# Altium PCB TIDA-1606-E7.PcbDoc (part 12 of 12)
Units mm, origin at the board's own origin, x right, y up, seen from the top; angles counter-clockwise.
Board outline 270 x 345 mm, 4 copper layers (Top Layer, Signal Layer 1, Signal Layer 2, Bottom Layer), stack 2.326 mm thick; 1282 components, 576 nets, 3628 pads, 4132 vias.
Unrouted connection lines stored in the file: 1719.
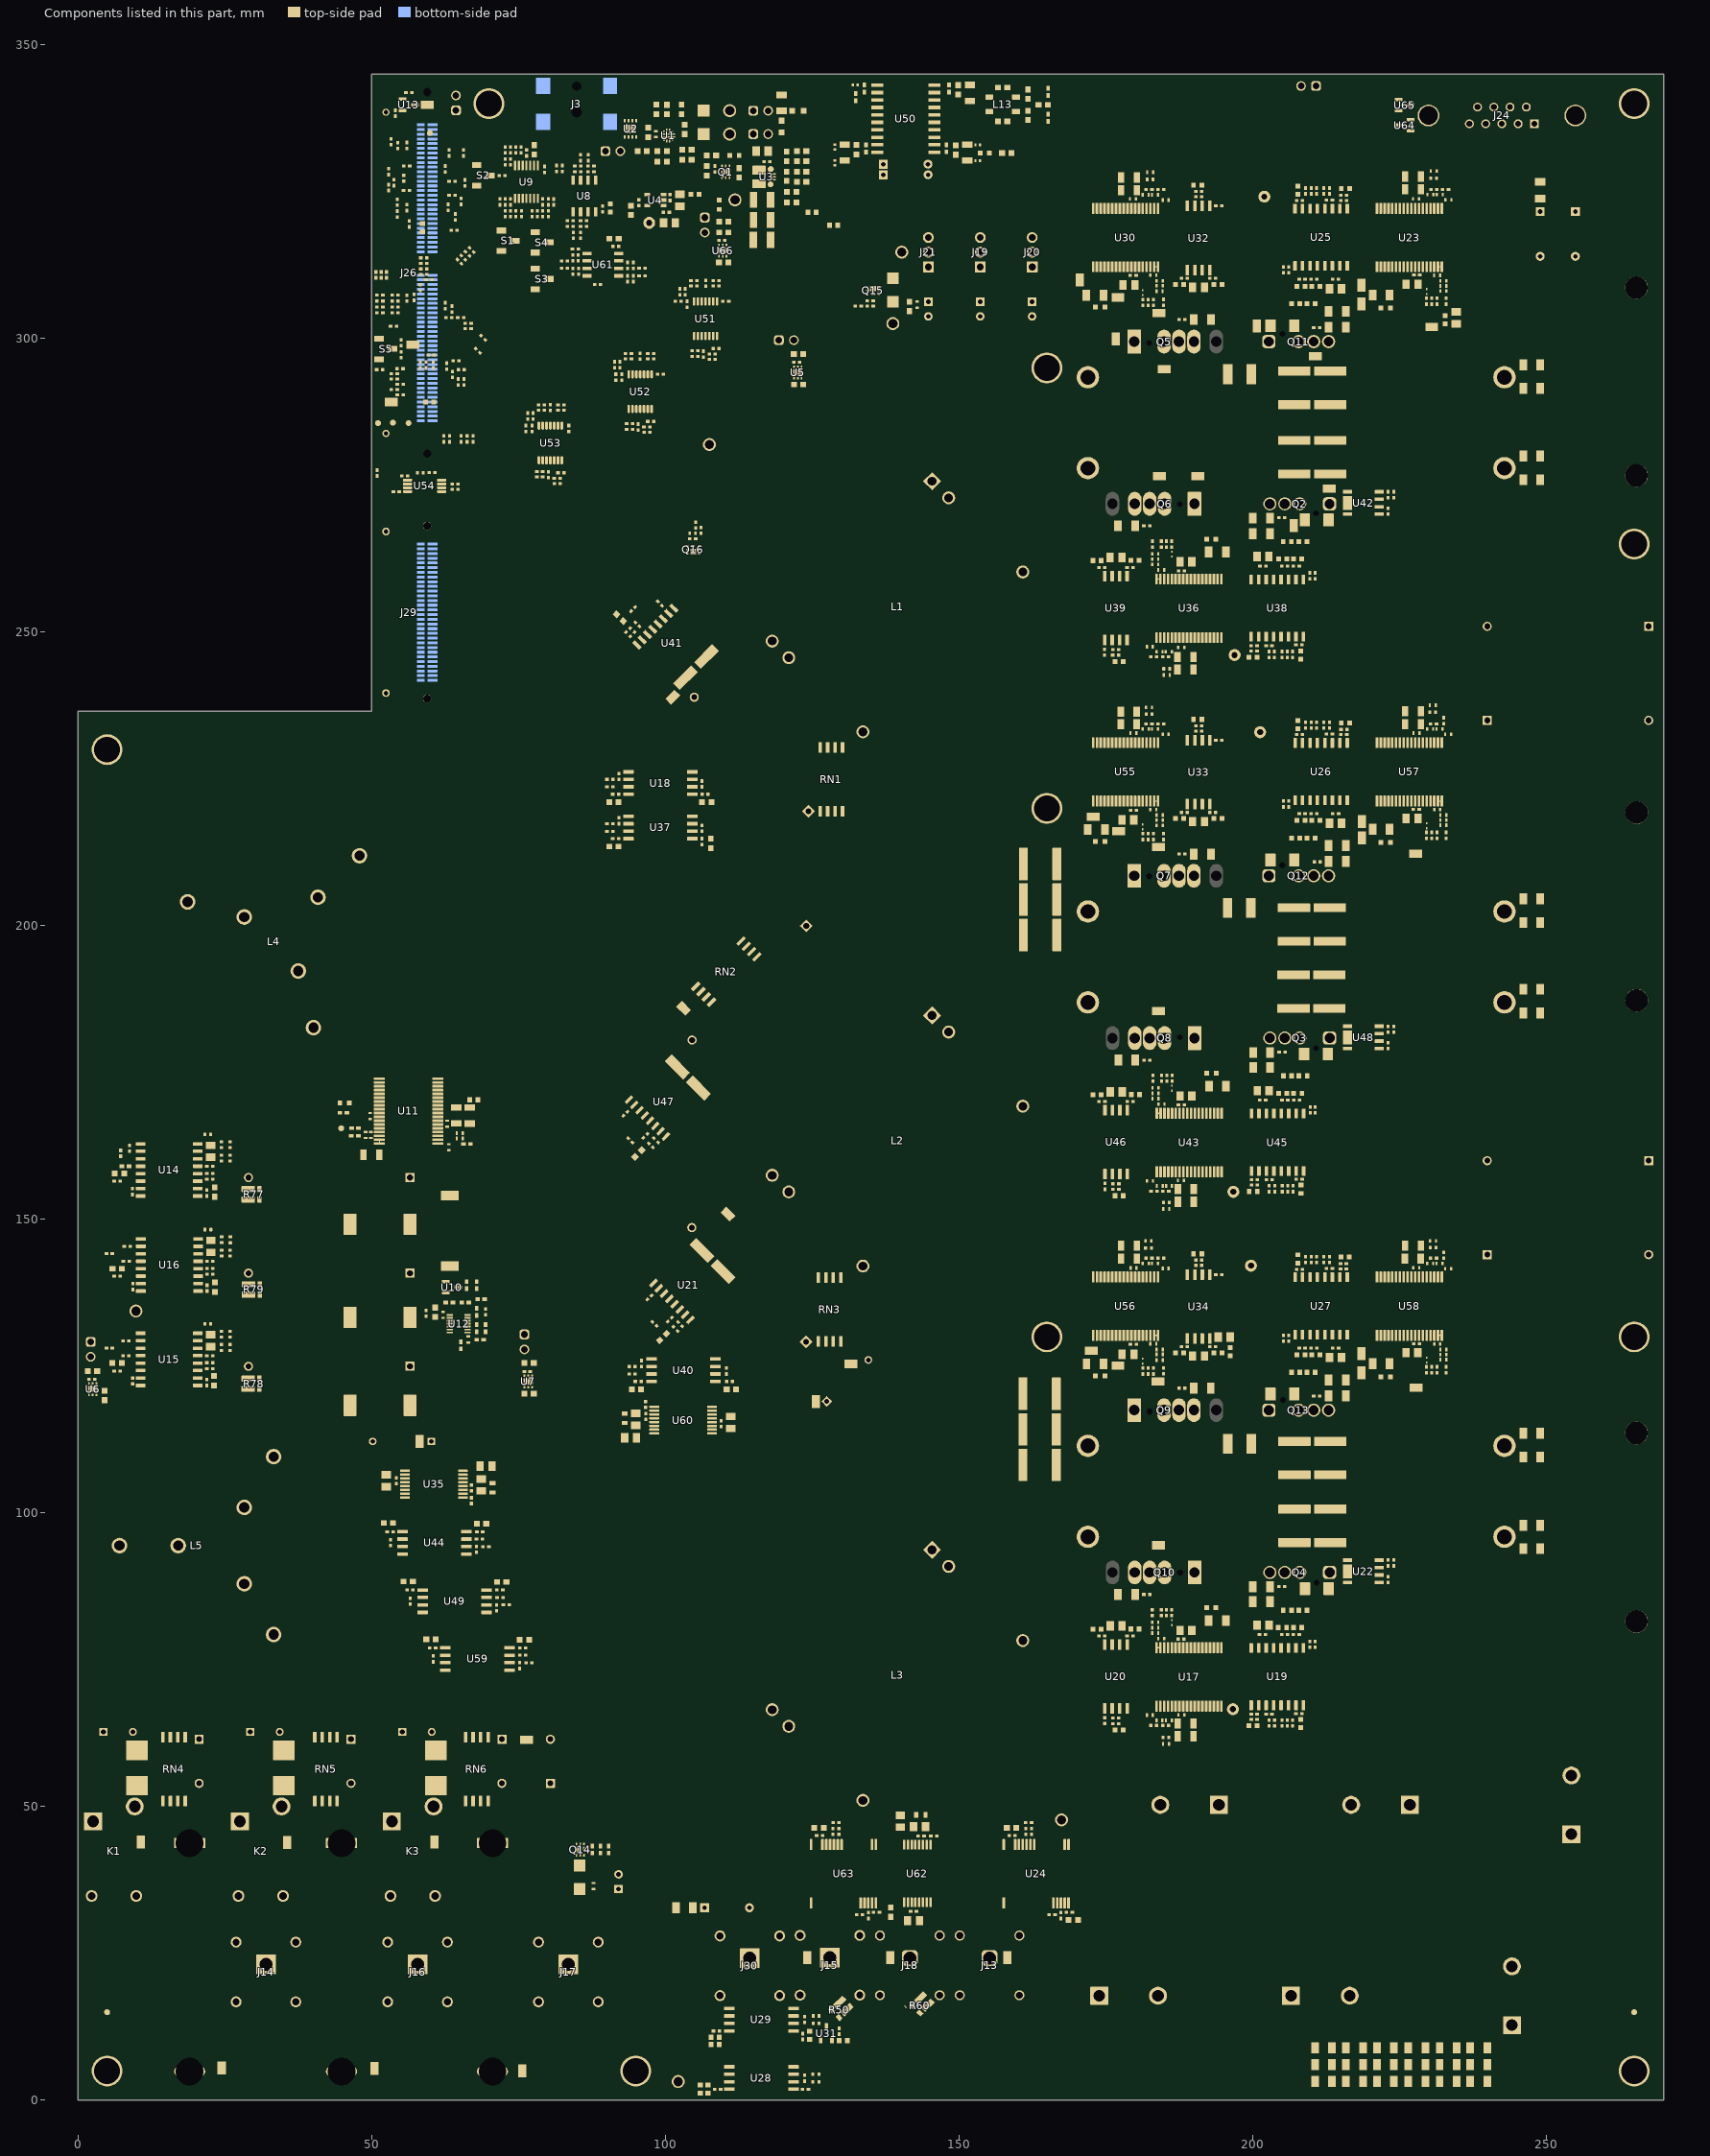
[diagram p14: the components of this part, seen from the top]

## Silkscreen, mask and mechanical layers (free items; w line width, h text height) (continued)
M2 Board Dimensions:
  rectangle: -15.925,-8.36 -6.4,-5.185
  rectangle: -19.1,-5.185 -15.925,-2.01
  lines w0.1: 176.163,271.85 179.973,271.85 ; 176.165,89.887 179.975,89.887 ; 176.165,180.882 179.975,180.882 ; 190.043,299.48 193.853,299.48 ; 190.045,117.516 193.855,117.516 ; 190.045,208.511 193.855,208.511
  lines w0.15: 58.402,264.985 58.402,285.985
  lines w0.178: -19.1,-5.185 6.3,-5.185 ; -15.925,-8.36 -15.925,-2.01 ; -12.75,-8.36 -12.75,-2.01 ; -6.4,-8.36 -6.4,-2.01 ; -0.05,-8.36 -0.05,-2.01 ; -19.1,-8.36 -19.1,-2.01 6.3,-2.01 6.3,-8.36 -19.1,-8.36
  lines w0.25: 1.213,275.363 1.213,342.615 ; 1.398,275.211 44.234,275.251 ; 1.398,342.8 44.248,342.742 ; 44.363,275.38 44.363,280.141 44.4,280.178 47.652,280.178 ; 44.375,342.615 44.375,337.891 44.501,337.891 ; 44.552,337.881 47.623,337.881 ; 48.311,278.355 48.311,278.718 ; 48.334,339.34 48.334,339.755 ; 48.428,278.177 50.405,278.177 ; 48.463,339.884 50.442,339.884 ; 50.566,339.727 50.566,335.382 56.434,335.382 ; 50.568,278.299 50.568,282.928 56.418,282.928 56.439,282.926 ; 51.432,309.542 56.439,309.542 ; 51.432,311.954 51.456,311.956 56.396,311.956 ; 56.56,312.078 56.56,335.233 ; 56.567,283.054 56.568,309.413
  lines w0.254: 1.213,275.363 ccw(c1.37,275.365) 1.398,275.211 ; 1.213,342.615 cw(c1.522,342.491) 1.398,342.8 ; 44.234,275.251 ccw(c44.233,275.38) 44.325,275.289 ccw(c44.236,275.38) 44.363,275.38 ; 44.248,342.742 cw(c44.248,342.615) 44.375,342.615 ; 44.501,337.891 cw(c44.502,337.764) 44.552,337.881 ; 47.623,337.881 ccw(c47.663,338.533) 47.671,337.879 ccw(c47.672,338.742) 48.36,339.263 cw(c48.458,339.339) 48.334,339.34 ; 47.652,280.178 cw(c47.649,279.315) 48.337,278.795 ccw(c48.437,278.718) 48.311,278.718 ; 48.312,278.355 ccw(c48.428,278.304) 48.428,278.177 ; 48.334,339.755 cw(c48.459,339.756) 48.371,339.845 cw(c48.464,339.755) 48.463,339.884 ; 50.405,278.177 ccw(c50.44,278.293) 50.441,278.172 ccw(c50.441,278.299) 50.568,278.299 ; 50.442,339.884 cw(c50.443,339.757) 50.566,339.727 ; 51.432,309.542 cw(c51.441,310.748) 51.432,311.954 ; 56.396,311.956 ccw(c56.432,312.072) 56.432,311.951 ccw(c56.432,312.078) 56.56,312.078 ; 56.434,335.382 cw(c56.434,335.254) 56.56,335.233 ; 56.439,282.926 ccw(c56.439,283.054) 56.567,283.054 ; 56.439,309.542 cw(c56.44,309.415) 56.53,309.504 cw(c56.438,309.411) 56.568,309.413
  text ".Layer_Name" at -4.444,-20.006 h0.76
M3 3D STEP Top:
  text ".Layer_Name" at -25.064,56.36 h0.76
M4 3D STEP Bottom:
  text ".Layer_Name" at -25.064,56.36 h0.76
M5 Assembly Top:
  lines w0.254: -26.517,-21.826 141.123,-21.826 ; -26.517,-16.662 141.174,-16.662 ; -26.517,-11.497 -26.517,-26.991 75.21,-26.991 141.174,-26.991 141.174,-11.497 -26.504,-11.497 -26.504,-26.991 13.514,-26.991 ; 36.094,-26.991 36.094,-11.497 ; 68.276,-16.662 68.276,-11.497 ; 89.612,-16.662 89.612,-11.497 ; 105.411,-27.156 105.411,-22.004
  text "COMPONENTS MARKED 'DNP' SHOULD NOT BE POPULATED." at 10.199,-6.29 h0.76
  text "ASSEMBLY VARIANT:" at 10.186,-9.224 h0.76
  text ".VariantName" at 36.501,-9.224 h0.76
  text "PCB VIEWED FROM TOP SIDE" at -24.904,-14.854 h0.76
  text "BOARD #:" at 37.999,-14.854 h0.76
  text ".PRJ_Number" at 51.855,-14.854 h0.76
  text "REV:" at 73.305,-14.854 h0.76
  text ".PCB_Rev" at 80.709,-14.854 h0.76
  text "SVN REV:" at 94.59,-14.854 h0.76
  text ".VersionControl_RevNumber" at 107.443,-14.854 h0.76
  text "Note: Isolated thermal pads are required for all 12x HV SiC FET assembly (to the heatsink)" at 169.799,-15.215 h1.52
  text "PLOT NAME =" at -24.904,-25.234 h0.76
  text ".plot_File_Name" at -4.444,-25.234 h0.76
  text "GENERATED    :" at 38.05,-25.234 h0.76
  text ".Print_Date" at 60.135,-25.234 h0.76
  text ".Print_Time" at 78.652,-25.234 h0.76
  text "TEXAS INSTRUMENTS" at 110.77,-25.234 h0.76
M6 Assembly Bottom:
  lines w0.254: -26.529,-16.674 141.161,-16.674 ; -26.479,-21.839 141.161,-21.839 ; 9.234,-27.169 9.234,-22.017 ; 25.033,-16.674 25.033,-11.51 ; 46.369,-16.674 46.369,-11.51 ; 78.55,-27.004 78.55,-11.51 ; 101.131,-27.004 141.149,-27.004 141.149,-11.51 -26.529,-11.51 -26.529,-27.004 39.434,-27.004 141.161,-27.004 141.161,-11.51
  text "COMPONENTS MARKED 'DNP' SHOULD NOT BE POPULATED." at 135.891,-6.277 h0.76
  text ".VariantName" at 109.373,-9.224 h0.76
  text "ASSEMBLY VARIANT:" at 135.764,-9.224 h0.76
  text ".VersionControl_RevNumber" at 7.202,-14.867 h0.76
  text "SVN REV:" at 20.054,-14.867 h0.76
  text ".PCB_Rev" at 33.935,-14.867 h0.76
  text "REV:" at 41.339,-14.867 h0.76
  text ".PRJ_Number" at 62.79,-14.867 h0.76
  text "BOARD #:" at 76.645,-14.867 h0.76
  text "PCB VIEWED FROM BOTTOM SIDE" at 139.548,-14.867 h0.76
  text "TEXAS INSTRUMENTS" at 3.874,-25.247 h0.76
  text ".Print_Time" at 35.993,-25.247 h0.76
  text ".Print_Date" at 54.509,-25.247 h0.76
  text "GENERATED    :" at 76.595,-25.247 h0.76
  text ".plot_File_Name" at 119.089,-25.247 h0.76
  text "PLOT NAME =" at 139.548,-25.247 h0.76
M9 Title Sheet:
  drawing of 56 lines, arcs and shapes, not listed
  text "1" at 7.782,341.687 h1.78
  text "2" at 92.254,341.687 h1.78
  text "3" at 176.836,341.687 h1.78
  text "4" at 261.545,341.687 h1.78
  text "5" at 346,341.687 h1.78
  text "6" at 430.709,341.687 h1.78
  text "A" at -30.86,296.526 h1.78
  text "A" at 469.52,296.526 h1.78
  text "B" at -30.86,201.276 h1.78
  text "B" at 469.52,201.276 h1.78
  text "C" at -30.86,106.026 h1.78
  text "C" at 469.52,106.026 h1.78
  text "D" at -30.86,10.776 h1.78
  text "D" at 469.52,10.776 h1.78
  text "PROJECT TITLE:" at 390.932,8.617 h1.14
  text ".PRJ_Title" at 392.202,5.231 h1.78
  text "DESIGNED FOR:" at 390.932,0.972 h1.14
  text ".PRJ_Customer" at 392.202,-2.584 h1.78
  text "FILE NAME:" at 390.932,-6.648 h1.14
  text ".PCB_File_Name_No_Path" at 392.202,-9.696 h1.78
  text "Texas Instruments (TI) and/or its licensors do not warrant the accuracy or completeness of this specification" at 264.707,-13.807 h1.14
  text "ENGINEER:" at 390.932,-14.014 h1.14
  text "LAYOUT BY:" at 429.159,-14.014 h1.14
  text "or any information contained therein. TI and/or its licensors do not warrant that this design will meet" at 263.564,-16.669 h1.14
  text ".PRJ_Engineer" at 392.202,-17.951 h1.78
  text ".PCB_Layout" at 430.442,-17.951 h1.78
  text "the specifications, will be suitable for your application or fit for any particular purpose, or will operate in" at 263.564,-19.53 h1.14
  text ".Layer_Name" at -4.444,-20.006 h0.76
  text "ALTIUM DESIGNER VERSION:" at 429.159,-21.888 h1.14
  text "an implementation. TI and/or its licensors do not warrant that the design is production worthy. You should" at 263.564,-22.392 h1.14
  text "completely validate and test your design implementation to confirm the system functionality for your application." at 264.707,-25.254 h1.14
  text ".print_Scale" at 392.202,-25.275 h1.78
  text ".Application_BuildNumber" at 430.442,-25.275 h1.78
  text "1" at 7.782,-31.693 h1.78
  text "2" at 92.254,-31.693 h1.78
  text "3" at 176.836,-31.693 h1.78
  text "4" at 261.545,-31.693 h1.78
  text "5" at 346,-31.693 h1.78
  text "6" at 430.709,-31.693 h1.78
M10 Fab Notes:
  drawing of 189 lines, arcs and shapes, not listed
  text "DESIGN INFORMATION" at 417.222,163.475 h0.76
  text "MIN. TRACK WIDTH:" at 400.85,160.119 h0.76
  text "8" at 428.694,160.119 h0.76
  text "MIL" at 432.625,160.119 h0.76
  text "1. 2-Oz Cu ON ALL LAYERS." at 273.678,159.491 h1.52
  text "8" at 428.694,157 h0.76
  text "MIN. CLEARANCE:" at 400.85,156.967 h0.76
  text "MIL" at 432.625,156.967 h0.76
  text "2. ALL VIAS ARE TENTED ON BOTH SIDES EXCEPT VIAS ON PAD." at 273.678,155.578 h1.52
  text "MIN. VIA PAD SIZE:" at 400.85,153.814 h0.76
  text "24" at 428.694,153.814 h0.76
  text "MIL" at 432.625,153.814 h0.76
  text "3. Vias have min annular ring of 5 mil (14 mil hole)" at 273.583,151.1 h1.52
  text "0.127mm (5MIL)" at 418.503,150.514 h0.76
  text "MINIMUM ANNULAR RING" at 392.487,150.306 h0.76
  text "EXTERNAL" at 436.486,150.306 h0.76
  text "PER" at 397.567,147.508 h0.76
  text "IPC-D-275 CLASS 2 LEVEL C" at 403.155,147.508 h0.76
  text "MIL, HOLES" at 440.956,144.956 h0.76
  text "+/-" at 430.988,144.738 h0.76
  text "+/-" at 452.68,144.738 h0.76
  text "REGISTRATION TOLERANCES:" at 392.487,144.711 h0.76
  text "METAL" at 422.962,144.711 h0.76
  text "5" at 437.597,144.711 h0.76
  text "3" at 458.755,144.711 h0.76
  text "MIL" at 461.708,144.711 h0.76
  text "4. Adjust the core layer (layer 6),  / so that the total pcb thickness is ~92 mil or 2.34 mm." at 273.456,143 h1.52
  text "HOLE SIZE TOLERANCE (UNLESS OTHERWISE SPECIFIED):" at 392.487,142.214 h0.76
  text "+/-" at 452.68,142.141 h0.76
  text "3" at 458.755,142.114 h0.76
  text "MIL" at 461.708,142.114 h0.76
  text "MATERIAL:" at 390.588,138.618 h0.76
  text "FR-4 High Tg" at 415.644,135.353 h0.76
  text "X" at 411.975,135.15 h0.76
  text "FR-408" at 401.282,135.035 h0.76
  text "OTHER" at 439.077,135.035 h0.76
  text "62 MIL (1.6mm) +/-10%" at 409.412,131.402 h0.76
  text "X" at 406.362,131.34 h0.76
  text "THICKNESS:" at 392.487,131.194 h0.76
  text "OTHER" at 442.049,131.194 h0.76
  text "TOLERANCE:" at 392.487,127.68 h0.76
  text "X" at 414.033,127.68 h0.76
  text "ANSI IPC-6012 TYPE 3 CLASS 2" at 418.554,127.68 h0.76
  text "OTHER +/-" at 418.554,124.018 h0.76
  text "BOW & TWIST:" at 392.487,120.33 h0.76
  text "X" at 414.033,120.33 h0.76
  text "ANSI IPC-6012 TYPE 3 CLASS 2" at 418.554,120.33 h0.76
  text "OTHER +/-" at 418.554,116.604 h0.76
  text "DRILLING:" at 390.588,113.286 h0.76
  text "NC_DRILL FILES" at 435.318,110.615 h0.76
  text "REFERENCE:" at 392.487,110.515 h0.76
  text "X" at 409.181,110.512 h0.76
  text "AS SHOWN" at 413.702,110.515 h0.76
  text "X" at 432.067,110.515 h0.76
  text "OTHER" at 442.887,106.901 h0.76
  text "PTH COPPER THICKNESS:" at 392.479,106.812 h0.76
  text "X" at 421.416,106.812 h0.76
  text "20-30 um" at 424.667,106.812 h0.76
  text "BOARD FINISH:" at 390.588,103.063 h0.76
  text "SILKSCREEN:" at 394.531,100.266 h0.76
  text "X" at 418.859,100.266 h0.76
  text "TOP" at 421.83,100.266 h0.76
  text "X" at 431.813,100.266 h0.76
  text "BOTTOM" at 434.81,100.266 h0.76
  text "SILKSCREEN COLOR:" at 394.531,96.324 h0.76
  text "X" at 418.833,96.324 h0.76
  text "WHITE" at 421.83,96.324 h0.76
  text "OTHER" at 434.81,96.324 h0.76
  text "X" at 422.161,92.68 h0.76
  text "GREEN" at 425.158,92.68 h0.76
  text "OTHER" at 440.855,92.68 h0.76
  text "SOLDER RESIST COLOR:" at 394.531,92.506 h0.76
  text "X" at 422.161,88.762 h0.76
  text "MATTE" at 425.158,88.762 h0.76
  text "SEMI-GLOSS" at 440.843,88.746 h0.76
  text "IMMERSION GOLD (ENIG)" at 417.538,84.374 h0.76
  text "ENEPIG" at 451.511,84.19 h0.76
  text "SURFACE FINISH:" at 390.588,84.165 h0.76
  text "X" at 413.017,84.165 h0.76
  text "IMM. TIN/SILVER OR EQUIV" at 398.959,80.677 h0.76
  text "OTHER" at 435.318,80.577 h0.76
  text "ARRAY/PANEL:" at 390.588,76.631 h0.76
  text "CUT AND TRIM PER M1 BOARD OUTLINE" at 417.538,76.422 h0.76
  text "N.C. ROUTE" at 417.538,72.968 h0.76
  text "X" at 435.013,72.968 h0.76
  text "V. SCORE" at 439.534,72.968 h0.76
  text "CERTIFICATION:" at 390.588,69.688 h0.76
  text "MATERIALS AND WORKMANSHIP FOR ALL PCBS" at 409.003,69.688 h0.76
  text "TO MEET OR EXCEED THE REQUIREMENTS OF:" at 409.003,67.299 h0.76
  text "X" at 399.796,64.032 h0.76
  text "ANSI IPC-A-600F CLASS ->" at 403.047,64.032 h0.76
  text "X" at 444.906,64.032 h0.76
  text "2" at 447.7,64.032 h0.76
  text "1" at 439.699,63.994 h0.76
  text "3" at 456.692,63.994 h0.76
  text "X" at 420.421,60.281 h0.76
  text "RoHS" at 423.672,60.281 h0.76
  text "OTHER" at 440.04,60.281 h0.76
  text "PER ORDER" at 450.125,60.281 h0.76
  text "ALL BOARDS MUST MEET OR EXCEED UL94-V0 REQUIREMENTS." at 391.288,56.374 h0.76
  text "PCB MUST BEAR THE UL94V-0 UL REGISTERED MATERIAL ID NUMBER" at 391.288,53.426 h0.76
  text "ADDITIONAL REQUIREMENTS:" at 390.588,49.122 h0.76
  text "MICROSECTION:" at 392.487,46.401 h0.76
  text "YES" at 415.493,46.401 h0.76
  text "REQUIRED" at 437.375,42.735 h0.76
  text "BARE BOARD ELEC. TEST:" at 392.487,42.663 h0.76
  text "NONE" at 425.653,42.663 h0.76
  text "X" at 434.378,42.663 h0.76
  text "PER ORDER" at 452.412,42.663 h0.76
  text "XX MIL VIAS REQUIRE NON-CONDUCTIVE FILL AND PLANARIZE" at 396.758,37.457 h1.5
  text "XX MIL VIAS REQUIRE CONDUCTIVE FILL AND PLANARIZE" at 396.962,34.816 h0.76
  text "OUTER XX MIL TRACES REQUIRE 50 OHM SINGLE-ENDED IMPEDANCE" at 396.937,30.666 h1.47
  text "LAYER 2 & 3 (INNER LAYERS) XX MIL WIDE, XX MIL SPACE / TRACES REQUIRE 100 OHM DIFFERENTIAL IMPEDANCE" at 396.733,24.679 h0.76
  text ".Layer_Name" at -4.444,-20.006 h0.76
M11 Gerber Information:
  lines w0.254: -26.517,-21.826 141.123,-21.826 ; -26.517,-16.662 141.174,-16.662 ; -26.517,-11.497 -26.517,-26.991 75.21,-26.991 141.174,-26.991 141.174,-11.497 -26.504,-11.497 -26.504,-26.991 13.514,-26.991 ; 36.094,-26.991 36.094,-11.497 ; 68.276,-16.662 68.276,-11.497 ; 89.612,-16.662 89.612,-11.497 ; 105.411,-27.156 105.411,-22.004
  text "ALL ARTWORK VIEWED FROM TOP SIDE" at -24.904,-14.854 h0.76
  text "BOARD #:" at 37.999,-14.854 h0.76
  text ".PRJ_Number" at 51.855,-14.854 h0.76
  text "REV:" at 73.305,-14.854 h0.76
  text ".PCB_Rev" at 80.709,-14.854 h0.76
  text "SVN REV:" at 94.59,-14.854 h0.76
  text ".VersionControl_RevNumber" at 107.443,-14.854 h0.76
  text "LAYER NAME =" at -24.904,-20.006 h0.76
  text "PLOT NAME =" at -24.904,-25.234 h0.76
  text ".plot_File_Name" at -4.444,-25.234 h0.76
  text "GENERATED    :" at 38.05,-25.234 h0.76
  text ".Print_Date" at 60.135,-25.234 h0.76
  text ".Print_Time" at 78.652,-25.234 h0.76
  text "TEXAS INSTRUMENTS" at 110.77,-25.234 h0.76
M12 Stackup:
  drawing of 295 lines, arcs and shapes, not listed
  text "Layer" at 278.291,202.997 h1.52
  text "Name" at 288.703,202.997 h1.52
  text "Material" at 312.572,202.997 h1.52
  text "Thickness" at 334.41,202.997 h1.52
  text "Constant" at 350.916,202.997 h1.52
  text "Board Layer Stack" at 365.391,202.997 h1.52
  text "1" at 278.291,199.949 h1.52
  text "Top Overlay" at 288.703,199.949 h1.52
  text "2" at 278.291,196.901 h1.52
  text "Top Solder" at 288.703,196.901 h1.52
  text "Solder Resist" at 312.572,196.901 h1.52
  text "0.39mil" at 334.41,196.901 h1.52
  text "3.5" at 350.916,196.901 h1.52
  text "3" at 278.291,193.853 h1.52
  text "Top Layer" at 288.703,193.853 h1.52
  text "Copper" at 312.572,193.853 h1.52
  text "2.36mil" at 334.41,193.853 h1.52
  text "4" at 278.291,190.805 h1.52
  text "Dielectric 1" at 288.703,190.805 h1.52
  text "FR-4" at 312.572,190.805 h1.52
  text "14.17mil" at 334.41,190.805 h1.52
  text "4.2" at 350.916,190.805 h1.52
  text "5" at 278.291,187.757 h1.52
  text "Signal Layer 1" at 288.703,187.757 h1.52
  text "Copper" at 312.572,187.757 h1.52
  text "2.76mil" at 334.41,187.757 h1.52
  text "6" at 278.291,184.709 h1.52
  text "Dielectric 2" at 288.703,184.709 h1.52
  text "FR-4" at 312.572,184.709 h1.52
  text "53.00mil" at 334.41,184.709 h1.52
  text "4.2" at 350.916,184.709 h1.52
  text "7" at 278.291,181.661 h1.52
  text "Signal Layer 2" at 288.703,181.661 h1.52
  text "Copper" at 312.572,181.661 h1.52
  text "2.76mil" at 334.41,181.661 h1.52
  text "8" at 278.291,178.613 h1.52
  text "Dielectric 3" at 288.703,178.613 h1.52
  text "FR-4" at 312.572,178.613 h1.52
  text "14.17mil" at 334.41,178.613 h1.52
  text "4.2" at 350.916,178.613 h1.52
  text "9" at 278.291,175.565 h1.52
  text "Bottom Layer" at 288.703,175.565 h1.52
  text "Copper" at 312.572,175.565 h1.52
  text "2.36mil" at 334.41,175.565 h1.52
  text "10" at 278.291,172.517 h1.52
  text "Bottom Solder" at 288.703,172.517 h1.52
  text "Solder Resist" at 312.572,172.517 h1.52
  text "0.39mil" at 334.41,172.517 h1.52
  text "3.5" at 350.916,172.517 h1.52
  text "11" at 278.291,169.469 h1.52
  text "Bottom Overlay" at 288.703,169.469 h1.52
  text ".Layer_Name" at -4.444,-20.006 h0.76
M13 Component Bodies Top:
  text ".Layer_Name" at -4.444,-20.006 h0.76
M14 Component Bodies Bottom:
  text ".Layer_Name" at -4.444,-20.006 h0.76
M15 Courtyards Top:
  text ".Layer_Name" at -4.444,-20.006 h0.76
M16 Courtyards Bottom:
  text ".Layer_Name" at -4.444,-20.006 h0.76
Drill Drawing:
  drawing of 165 lines, arcs and shapes, not listed
  text "Symbol" at 281.267,335.369 h1.83
  text "Count" at 294.116,335.369 h1.83
  text "Hole Size" at 310.876,335.369 h1.83
  text "Plated" at 340.077,335.369 h1.83
  text "Hole Type" at 352.926,335.369 h1.83
  text "Drill Layer Pair" at 371.565,335.369 h1.83
  text "Via/Pad" at 409.653,335.369 h1.83
  text "Pad Shape" at 424.636,335.369 h1.83
  text "Template" at 452.314,335.369 h1.83
  text "Description" at 484.816,335.369 h1.83
  text "Hole Tolerance (+)" at 506.502,335.369 h1.83
  text "Hole Tolerance (-)" at 540.375,335.369 h1.83
  text "1" at 294.116,331.559 h1.52
  text "62.99mil (1.600mm)" at 310.876,331.559 h1.52
  text "NPTH" at 340.077,331.559 h1.52
  text "Round" at 352.926,331.559 h1.52
  text "Top Layer - Bottom Layer" at 371.565,331.559 h1.52
  text "Pad" at 409.653,331.559 h1.52
  text "Rounded" at 424.636,331.559 h1.52
  text "c100hn160" at 452.314,331.559 h1.52
  text "B" at 280.528,331.305 h1.69
  text "1" at 294.116,327.749 h1.52
  text "70.87mil (1.800mm)" at 310.876,327.749 h1.52
  text "NPTH" at 340.077,327.749 h1.52
  text "Round" at 352.926,327.749 h1.52
  text "Top Layer - Bottom Layer" at 371.565,327.749 h1.52
  text "Pad" at 409.653,327.749 h1.52
  text "Rounded" at 424.636,327.749 h1.52
  text "c152hn180" at 452.314,327.749 h1.52
  text "A" at 280.528,327.495 h1.69
  text "2" at 294.116,323.939 h1.52
  text "31.89mil (0.810mm)" at 310.876,323.939 h1.52
  text "PTH" at 340.077,323.939 h1.52
  text "Round" at 352.926,323.939 h1.52
  text "Top Layer - Bottom Layer" at 371.565,323.939 h1.52
  text "Pad" at 409.653,323.939 h1.52
  text "Rounded" at 424.636,323.939 h1.52
  text "c122h81(Tol5-5)" at 452.314,323.939 h1.52
  text "1.97mil (0.050mm)" at 506.502,323.939 h1.52
  text "1.97mil (0.050mm)" at 540.375,323.939 h1.52
  text "I" at 280.81,323.685 h1.69
  text "2" at 294.116,320.129 h1.52
  text "31.89mil (0.810mm)" at 310.876,320.129 h1.52
  text "PTH" at 340.077,320.129 h1.52
  text "Round" at 352.926,320.129 h1.52
  text "Top Layer - Bottom Layer" at 371.565,320.129 h1.52
  text "Pad" at 409.653,320.129 h1.52
  text "Rounded" at 424.636,320.129 h1.52
  text "c131h81m131p100131" at 452.314,320.129 h1.52
  text "M" at 280.528,319.875 h1.69
  text "2" at 294.116,316.319 h1.52
  text "55.12mil (1.400mm)" at 310.876,316.319 h1.52
  text "NPTH" at 340.077,316.319 h1.52
  text "Round" at 352.926,316.319 h1.52
  text "Top Layer - Bottom Layer" at 371.565,316.319 h1.52
  text "Pad" at 409.653,316.319 h1.52
  text "Rounded" at 424.636,316.319 h1.52
  text "c140hn140m140p100140" at 452.314,316.319 h1.52
  text "N" at 280.528,316.065 h1.69
  text "2" at 294.116,312.509 h1.52
  text "55.12mil (1.400mm)" at 310.876,312.509 h1.52
  text "NPTH" at 340.077,312.509 h1.52
  text "Round" at 352.926,312.509 h1.52
  text "Top Layer - Bottom Layer" at 371.565,312.509 h1.52
  text "Pad" at 409.653,312.509 h1.52
  text "Rounded" at 424.636,312.509 h1.52
  text "c110hn140m150(Tol5-5)" at 452.314,312.509 h1.52
  text "1.97mil (0.050mm)" at 506.502,312.509 h1.52
  text "1.97mil (0.050mm)" at 540.375,312.509 h1.52
  text "C" at 280.528,312.255 h1.69
  text "2" at 294.116,308.699 h1.52
  text "125.98mil (3.200mm)" at 310.876,308.699 h1.52
  text "PTH" at 340.077,308.699 h1.52
  text "Round" at 352.926,308.699 h1.52
  text "Top Layer - Bottom Layer" at 371.565,308.699 h1.52
  text "Pad" at 409.653,308.699 h1.52
  text "Rounded" at 424.636,308.699 h1.52
  text "c370h320" at 452.314,308.699 h1.52
  text "H" at 280.528,308.445 h1.69
  text "4" at 294.116,304.889 h1.52
  text "31.50mil (0.800mm)" at 310.876,304.889 h1.52
  text "PTH" at 340.077,304.889 h1.52
  text "Round" at 352.926,304.889 h1.52
  text "Top Layer - Bottom Layer" at 371.565,304.889 h1.52
  text "Pad" at 409.653,304.889 h1.52
  text "(Mixed)" at 424.636,304.889 h1.52
  text "(Mixed)" at 452.314,304.889 h1.52
  text "J" at 280.528,304.635 h1.69
  text "6" at 294.116,301.079 h1.52
  text "33.47mil (0.850mm)" at 310.876,301.079 h1.52
  text "PTH" at 340.077,301.079 h1.52
  text "Round" at 352.926,301.079 h1.52
  text "Top Layer - Bottom Layer" at 371.565,301.079 h1.52
  text "Pad" at 409.653,301.079 h1.52
  text "(Mixed)" at 424.636,301.079 h1.52
  text "(Mixed)" at 452.314,301.079 h1.52
  text "6" at 294.116,297.269 h1.52
  text "51.18mil (1.300mm)" at 310.876,297.269 h1.52
  text "PTH" at 340.077,297.269 h1.52
  text "Round" at 352.926,297.269 h1.52
  text "Top Layer - Bottom Layer" at 371.565,297.269 h1.52
  text "Pad" at 409.653,297.269 h1.52
  text "Rounded" at 424.636,297.269 h1.52
  text "c200h130m200p100200" at 452.314,297.269 h1.52
  text "E" at 280.528,297.015 h1.69
  text "6" at 294.116,293.459 h1.52
  text "152.76mil (3.880mm)" at 310.876,293.459 h1.52
  text "NPTH" at 340.077,293.459 h1.52
  text "Round" at 352.926,293.459 h1.52
  text "Top Layer - Bottom Layer" at 371.565,293.459 h1.52
  text "Pad" at 409.653,293.459 h1.52
  text "Rounded" at 424.636,293.459 h1.52
  text "c388hn388m388p100388" at 452.314,293.459 h1.52
  text "6" at 294.116,289.649 h1.52
  text "185.04mil (4.700mm)" at 310.876,289.649 h1.52
  text "PTH" at 340.077,289.649 h1.52
  text "Slot" at 352.926,289.649 h1.52
  text "Top Layer - Bottom Layer" at 371.565,289.649 h1.52
  text "Pad" at 409.653,289.649 h1.52
  text "Rounded Rectangle" at 424.636,289.649 h1.52
  text "(Mixed)" at 452.314,289.649 h1.52
  text "D" at 280.528,289.395 h1.69
  text "7" at 294.116,285.839 h1.52
  text "40.00mil (1.016mm)" at 310.876,285.839 h1.52
  text "PTH" at 340.077,285.839 h1.52
  text "Round" at 352.926,285.839 h1.52
  text "Top Layer - Bottom Layer" at 371.565,285.839 h1.52
  text "Pad" at 409.653,285.839 h1.52
  text "Rounded" at 424.636,285.839 h1.52
  text "c203h102" at 452.314,285.839 h1.52
  text "7" at 294.116,282.029 h1.52
  text "86.61mil (2.200mm)" at 310.876,282.029 h1.52
  text "PTH" at 340.077,282.029 h1.52
  text "Round" at 352.926,282.029 h1.52
  text "Top Layer - Bottom Layer" at 371.565,282.029 h1.52
  text "Pad" at 409.653,282.029 h1.52
  text "Rounded Rectangle" at 424.636,282.029 h1.52
  text "(Mixed)" at 452.314,282.029 h1.52
  text "8" at 294.116,278.219 h1.52
  text "31.00mil (0.787mm)" at 310.876,278.219 h1.52
  text "PTH" at 340.077,278.219 h1.52
  text "Round" at 352.926,278.219 h1.52
  text "Top Layer - Bottom Layer" at 371.565,278.219 h1.52
  text "Pad" at 409.653,278.219 h1.52
  text "(Mixed)" at 424.636,278.219 h1.52
  text "(Mixed)" at 452.314,278.219 h1.52
  text "9" at 294.116,274.409 h1.52
  text "63.00mil (1.600mm)" at 310.876,274.409 h1.52
  text "PTH" at 340.077,274.409 h1.52
  text "Round" at 352.926,274.409 h1.52
  text "Top Layer - Bottom Layer" at 371.565,274.409 h1.52
  text "Pad" at 409.653,274.409 h1.52
  text "Rounded" at 424.636,274.409 h1.52
  text "c221h160" at 452.314,274.409 h1.52
  text "L" at 280.528,274.155 h1.69
  text "10" at 294.116,270.599 h1.52
  text "30.00mil (0.762mm)" at 310.876,270.599 h1.52
  text "PTH" at 340.077,270.599 h1.52
  text "Round" at 352.926,270.599 h1.52
  text "Top Layer - Bottom Layer" at 371.565,270.599 h1.52
  text "Pad" at 409.653,270.599 h1.52
  text "(Mixed)" at 424.636,270.599 h1.52
  text "(Mixed)" at 452.314,270.599 h1.52
  text "11" at 294.116,266.789 h1.52
  text "173.23mil (4.400mm)" at 310.876,266.789 h1.52
  text "NPTH" at 340.077,266.789 h1.52
  text "Round" at 352.926,266.789 h1.52
  text "Top Layer - Bottom Layer" at 371.565,266.789 h1.52
  text "Pad" at 409.653,266.789 h1.52
  text "Rounded" at 424.636,266.789 h1.52
  text "c440hn440m440p100440" at 452.314,266.789 h1.52
  text "12" at 294.116,262.979 h1.52
  text "39.37mil (1.000mm)" at 310.876,262.979 h1.52
  text "NPTH" at 340.077,262.979 h1.52
  text "Slot" at 352.926,262.979 h1.52
  text "Top Layer - Bottom Layer" at 371.565,262.979 h1.52
  text "Pad" at 409.653,262.979 h1.52
  text "Rounded" at 424.636,262.979 h1.52
  text "c-100hn100_800" at 452.314,262.979 h1.52
  text "R" at 280.528,262.725 h1.69
  text "12" at 294.116,259.169 h1.52
  text "68.90mil (1.750mm)" at 310.876,259.169 h1.52
  text "PTH" at 340.077,259.169 h1.52
  text "Round" at 352.926,259.169 h1.52
  text "Top Layer - Bottom Layer" at 371.565,259.169 h1.52
  text "Pad" at 409.653,259.169 h1.52
  text "Rounded" at 424.636,259.169 h1.52
  text "c265h175m265p100265" at 452.314,259.169 h1.52
  text "12" at 294.116,255.359 h1.52
  text "98.43mil (2.500mm)" at 310.876,255.359 h1.52
  text "PTH" at 340.077,255.359 h1.52
  text "Round" at 352.926,255.359 h1.52
  text "Top Layer - Bottom Layer" at 371.565,255.359 h1.52
  text "Pad" at 409.653,255.359 h1.52
  text "Rounded" at 424.636,255.359 h1.52
  text "c380h250m380p100380" at 452.314,255.359 h1.52
  text "F" at 280.528,255.105 h1.69
  text "15" at 294.116,251.549 h1.52
  text "16.00mil (0.406mm)" at 310.876,251.549 h1.52
  text "PTH" at 340.077,251.549 h1.52
  text "Round" at 352.926,251.549 h1.52
  text "Top Layer - Bottom Layer" at 371.565,251.549 h1.52
  text "Via" at 409.653,251.549 h1.52
  text "Rounded" at 424.636,251.549 h1.52
  text "v86h41m0mx0" at 452.314,251.549 h1.52
  text "18" at 294.116,247.739 h1.52
  text "45.28mil (1.150mm)" at 310.876,247.739 h1.52
  text "PTH" at 340.077,247.739 h1.52
  text "Round" at 352.926,247.739 h1.52
  text "Top Layer - Bottom Layer" at 371.565,247.739 h1.52
  text "Pad" at 409.653,247.739 h1.52
  text "(Mixed)" at 424.636,247.739 h1.52
  text "(Mixed)" at 452.314,247.739 h1.52
  text "K" at 280.528,247.485 h1.69
  text "18" at 294.116,243.929 h1.52
  text "59.06mil (1.500mm)" at 310.876,243.929 h1.52
  text "PTH" at 340.077,243.929 h1.52
  text "Round" at 352.926,243.929 h1.52
  text "Top Layer - Bottom Layer" at 371.565,243.929 h1.52
  text "Pad" at 409.653,243.929 h1.52
  text "(Mixed)" at 424.636,243.929 h1.52
  text "(Mixed)" at 452.314,243.929 h1.52
  text "18" at 294.116,240.119 h1.52
  text "78.74mil (2.000mm)" at 310.876,240.119 h1.52
  text "PTH" at 340.077,240.119 h1.52
  text "Round" at 352.926,240.119 h1.52
  text "Top Layer - Bottom Layer" at 371.565,240.119 h1.52
  text "Pad" at 409.653,240.119 h1.52
  text "(Mixed)" at 424.636,240.119 h1.52
  text "(Mixed)" at 452.314,240.119 h1.52
  text "24" at 294.116,236.309 h1.52
  text "66.93mil (1.700mm)" at 310.876,236.309 h1.52
  text "PTH" at 340.077,236.309 h1.52
  text "Round" at 352.926,236.309 h1.52
  text "Top Layer - Bottom Layer" at 371.565,236.309 h1.52
  text "Pad" at 409.653,236.309 h1.52
  text "(Mixed)" at 424.636,236.309 h1.52
  text "(Mixed)" at 452.314,236.309 h1.52
  text "30" at 294.116,232.499 h1.52
  text "70.08mil (1.780mm)" at 310.876,232.499 h1.52
  text "PTH" at 340.077,232.499 h1.52
  text "Round" at 352.926,232.499 h1.52
  text "Top Layer - Bottom Layer" at 371.565,232.499 h1.52
  text "Pad" at 409.653,232.499 h1.52
  text "Rounded Rectangle" at 424.636,232.499 h1.52
  text "(Mixed)" at 452.314,232.499 h1.52
  text "37" at 294.116,228.689 h1.52
  text "39.37mil (1.000mm)" at 310.876,228.689 h1.52
  text "PTH" at 340.077,228.689 h1.52
  text "Round" at 352.926,228.689 h1.52
  text "Top Layer - Bottom Layer" at 371.565,228.689 h1.52
  text "Pad" at 409.653,228.689 h1.52
  text "(Mixed)" at 424.636,228.689 h1.52
  text "(Mixed)" at 452.314,228.689 h1.52
  text "G" at 280.528,228.435 h1.69
  text "37" at 294.116,224.879 h1.52
  text "47.24mil (1.200mm)" at 310.876,224.879 h1.52
  text "PTH" at 340.077,224.879 h1.52
  text "Round" at 352.926,224.879 h1.52
  text "Top Layer - Bottom Layer" at 371.565,224.879 h1.52
  text "Pad" at 409.653,224.879 h1.52
  text "(Mixed)" at 424.636,224.879 h1.52
  text "(Mixed)" at 452.314,224.879 h1.52
  text "4117" at 294.116,221.069 h1.52
  text "14.00mil (0.356mm)" at 310.876,221.069 h1.52
  text "PTH" at 340.077,221.069 h1.52
  text "Round" at 352.926,221.069 h1.52
  text "Top Layer - Bottom Layer" at 371.565,221.069 h1.52
  text "Via" at 409.653,221.069 h1.52
  text "Rounded" at 424.636,221.069 h1.52
  text "(Mixed)" at 452.314,221.069 h1.52
  text "Q" at 280.528,220.815 h1.69
  text "4442 Total" at 294.116,217.259 h1.52
  text "Slot definitions :" at 281.267,213.576 h1.52
  text "Routed Path Length" at 307.497,213.576 h1.52
  text "= Calculated from tool start centre position to tool end centre position." at 335.505,213.576 h1.52
  text "Hole Length" at 307.497,211.037 h1.52
  text "= Routed Path Length + Tool Size = Slot length as defined in the PCB layout" at 325.094,211.037 h1.52
  text ".Layer_Name" at -4.444,-20.006 h0.76
M17 Embedded Cavity:
  text ".Layer_Name" at -4.444,-20.006 h0.76
M18 Embedded Assembly:
  text ".Layer_Name" at -4.444,-20.006 h0.76
M19 Embedded Keepout:
  text ".Layer_Name" at -4.698,-20.006 h0.76

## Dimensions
0,236.5 to 50,236.5 on M2 Board Dimensions
50,345 to 50,236.5 on M2 Board Dimensions
58.402,285.985 to 58.402,264.985 on M2 Board Dimensions
244.878,306.163 to 244.878,319.847 on M2 Board Dimensions
216.2,271.995 to 213.137,271.85 on M2 Board Dimensions
190.133,271.85 to 193.073,271.85 on M2 Board Dimensions
179.883,299.48 to 176.943,296.596 on M2 Board Dimensions
244.878,286.165 to 244.878,306.163 on M2 Board Dimensions
169.878,286.165 to 170.022,295.98 on M2 Board Dimensions
202.811,299.48 to 193.853,299.48 on M2 Board Dimensions
202.811,299.48 to 169.811,309.982 on M2 Board Dimensions
169.883,299.48 to 179.883,299.48 on M2 Board Dimensions
179.883,299.48 to 170.022,295.98 on M2 Board Dimensions
270,345 to 270.002,0 on M2 Board Dimensions
0,0 to 270,0 on M2 Board Dimensions
-19.1,-8.36 to 6.3,-8.36 on M2 Board Dimensions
